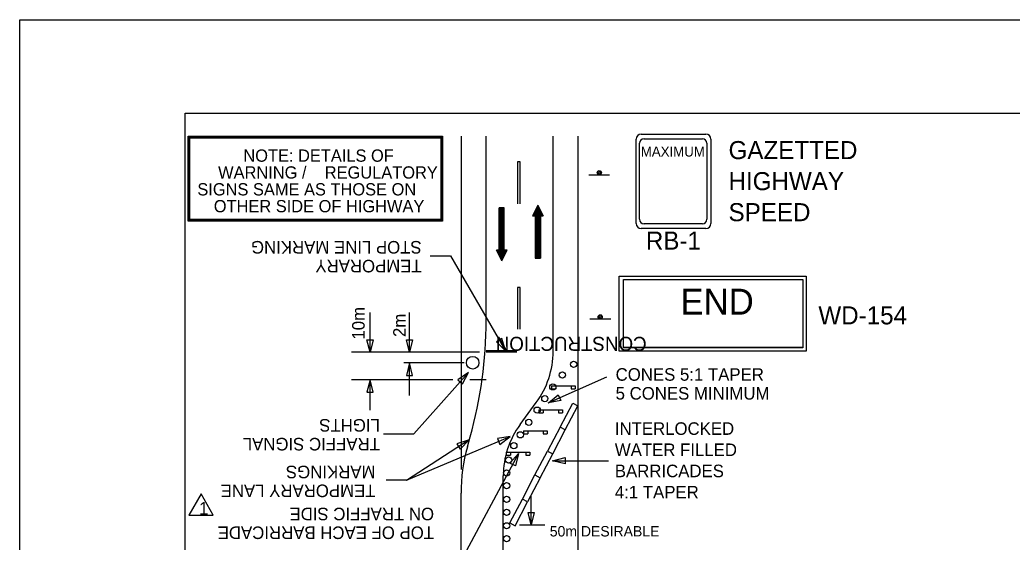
# Model space of a CAD drawing. Extents: x 2170 to 2386, y 134 to 413.
# Drawn here: x 2169.6 to 2284.4, y 352.3 to 412.8 of the extents above; entities that cross this region are included whole.
import ezdxf

# ---------------------------------------------------------------- set-up
doc = ezdxf.new("R2010")
doc.units = 0
for name, color, linetype in [('Level 1', 7, 'Continuous'), ('Level 10', 7, 'Continuous'), ('Level 2', 7, 'Continuous'), ('Level 44', 7, 'Continuous'), ('Level 5', 7, 'Continuous'), ('Level 60', 7, 'Continuous'), ('Level 7', 7, 'Continuous')]:
    doc.layers.add(name, color=color, linetype=linetype)

# ---------------------------------------------------------------- blocks, each defined once
blk = doc.blocks.new('END')
at = {"layer": 'Level 2'}
for points in [[(0, 8.676), (21.598, 8.676), (21.598, 0), (0, 0)], [(0.511, 8.287), (21.224, 8.287), (21.224, 0.397), (0.511, 0.397)]]:
    blk.add_lwpolyline(points, close=True, dxfattribs=at)
at = {"layer": 'Level 44'}
for s, height, rotation, p in [('END', 3, 359.99999, (7.085, 4.219)), ('CONSTRUCTION', 1.62, 179.99999, (3.164, 1.653))]:
    blk.add_text(s, height=height, rotation=rotation, dxfattribs=at).set_placement(p)
blk = doc.blocks.new('BARRIC')
at = {"layer": 'Level 2'}
for p, q in [((7.12, 10.29), (8.9, 12.87)), ((8.9, 12.87), (9.45, 12.48)), ((7.67, 9.91), (9.45, 12.48)), ((3.56, 5.15), (5.34, 7.72)), ((4.12, 4.76), (5.9, 7.33)), ((0, 0), (1.78, 2.57)), ((0.56, -0.39), (2.34, 2.19)), ((0, 0), (0.56, -0.39))]:
    blk.add_line(p, q, dxfattribs=at)
at = {"layer": 'Level 44'}
for p, q in [((7.12, 10.29), (5.34, 7.72)), ((5.9, 7.33), (7.67, 9.91)), ((7.67, 9.91), (7.12, 10.29)), ((5.34, 7.72), (5.9, 7.33)), ((1.78, 2.57), (3.56, 5.15)), ((4.12, 4.76), (2.34, 2.19)), ((3.56, 5.15), (4.12, 4.76)), ((2.34, 2.19), (1.78, 2.57))]:
    blk.add_line(p, q, dxfattribs=at)
blk = doc.blocks.new('REV1')
at = {"layer": 'Level 1'}
blk.add_lwpolyline([(0.114, 1.689), (-1.305, -0.781), (1.533, -0.781)], close=True, dxfattribs=at)
blk.add_text('1', height=1.448, rotation=360, dxfattribs=at).set_placement((-0.113, -0.724))

msp = doc.modelspace()

# ---------------------------------------------------------------- linework, layer by layer
at = {"layer": 'Level 10'}
for p, q in [((2220.64, 399.31), (2220.64, 360.72)), ((2223.55, 377.96), (2223.55, 399.31)), ((2231.29, 374.39), (2231.29, 399.28)), ((2234.19, 349.72), (2234.19, 399.31)), ((2225.04, 386.11), (2225.04, 391.01)), ((2225.65, 391.01), (2225.04, 391.01)), ((2225.04, 385.49), (2225.04, 391.01)), ((2225.12, 385.34), (2225.12, 391.01)), ((2225.19, 385.19), (2225.19, 391.01)), ((2225.27, 385.03), (2225.27, 391.01)), ((2225.35, 384.88), (2225.35, 391.01)), ((2225.42, 385.03), (2225.42, 391.01)), ((2225.5, 385.19), (2225.5, 391.01)), ((2225.58, 385.34), (2225.58, 391.01)), ((2225.65, 386.11), (2225.65, 391.01)), ((2225.65, 385.49), (2225.65, 391.01)), ((2229.54, 391.31), (2228.92, 390.08)), ((2229, 390.23), (2229, 390.08)), ((2229.08, 390.38), (2229.08, 390.08)), ((2229.15, 390.54), (2229.15, 390.08)), ((2229.23, 390.69), (2229.23, 385.17)), ((2229.31, 390.84), (2229.31, 385.17)), ((2229.38, 391), (2229.38, 385.17)), ((2229.46, 391.15), (2229.46, 385.17)), ((2229.54, 391.31), (2229.54, 385.17)), ((2229.54, 391.31), (2230.15, 390.08)), ((2229.61, 391.15), (2229.61, 385.17)), ((2229.69, 391), (2229.69, 385.17)), ((2229.77, 390.84), (2229.77, 385.17)), ((2229.84, 390.69), (2229.84, 385.17)), ((2229.92, 390.54), (2229.92, 390.08)), ((2230, 390.38), (2230, 390.08)), ((2230.07, 390.23), (2230.07, 390.08)), ((2228.92, 390.08), (2229.23, 390.08)), ((2229.23, 390.08), (2229.23, 385.17)), ((2229.84, 390.08), (2229.84, 385.17)), ((2229.84, 390.08), (2230.15, 390.08)), ((2225.35, 384.88), (2224.73, 386.11)), ((2225.04, 386.11), (2224.73, 386.11)), ((2224.81, 385.95), (2224.81, 386.11)), ((2224.89, 385.8), (2224.89, 386.11)), ((2224.96, 385.64), (2224.96, 386.11)), ((2225.35, 384.88), (2225.96, 386.11)), ((2225.96, 386.11), (2225.65, 386.11)), ((2225.73, 385.64), (2225.73, 386.11)), ((2225.81, 385.8), (2225.81, 386.11)), ((2225.88, 385.95), (2225.88, 386.11)), ((2217.08, 385.45), (2219.41, 385.45)), ((2219.41, 385.45), (2225.77, 374.45)), ((2229.23, 385.17), (2229.84, 385.17)), ((2210.12, 374.3), (2210.12, 378.89)), ((2214.68, 374.3), (2214.68, 378.89)), ((2222.79, 374.3), (2207.98, 374.3)), ((2227.09, 374.45), (2223.55, 374.45)), ((2227.09, 374.4), (2223.55, 374.4)), ((2227.09, 374.35), (2223.55, 374.35)), ((2227.09, 374.3), (2223.55, 374.3)), ((2221.02, 373.08), (2214.04, 373.08)), ((2214.68, 369.29), (2214.68, 373.08)), ((2215.2, 364.87), (2221.5, 371.95)), ((2219.69, 371.11), (2207.98, 371.11)), ((2210.12, 367.61), (2210.12, 371.11)), ((2223.55, 371.11), (2221.66, 371.11)), ((2231.11, 370.4), (2233.85, 370.4)), ((2231.11, 370.4), (2231.11, 370.06)), ((2231.11, 370.06), (2231.6, 370.06)), ((2231.6, 370.4), (2231.6, 370.06)), ((2233.37, 370.4), (2233.37, 370.06)), ((2233.37, 370.06), (2233.85, 370.06)), ((2233.85, 370.4), (2233.85, 370.06)), ((2227.48, 365.93), (2229.34, 368.47)), ((2229.64, 367.62), (2232.38, 367.62)), ((2229.64, 367.62), (2229.64, 367.28)), ((2229.64, 367.28), (2230.13, 367.28)), ((2230.13, 367.62), (2230.13, 367.28)), ((2231.9, 367.62), (2231.9, 367.28)), ((2231.9, 367.28), (2232.38, 367.28)), ((2232.38, 367.62), (2232.38, 367.28)), ((2227.88, 365.2), (2230.61, 365.2)), ((2227.88, 365.2), (2227.88, 364.86)), ((2228.36, 365.2), (2228.36, 364.86)), ((2230.13, 365.2), (2230.13, 364.86)), ((2230.61, 365.2), (2230.61, 364.86)), ((2211.67, 364.87), (2215.2, 364.87)), ((2221.58, 364.16), (2214.33, 359.46)), ((2214.35, 359.48), (2226.33, 364.54)), ((2221.38, 363.36), (2221.7, 364.51)), ((2227.88, 364.86), (2228.36, 364.86)), ((2230.13, 364.86), (2230.61, 364.86)), ((2225.87, 362.73), (2228.6, 362.73)), ((2225.87, 362.73), (2225.87, 362.39)), ((2226.35, 362.73), (2226.35, 362.39)), ((2228.12, 362.73), (2228.12, 362.39)), ((2228.6, 362.73), (2228.6, 362.39)), ((2227.3, 362.59), (2213.95, 337.69)), ((2225.87, 362.39), (2226.35, 362.39)), ((2228.12, 362.39), (2228.6, 362.39)), ((2231.22, 361.75), (2237.7, 361.75)), ((2214.33, 359.48), (2211.99, 359.48)), ((2220.64, 353.23), (2220.64, 357.98)), ((2228.76, 354.31), (2228.76, 357.65)), ((2227.42, 354.31), (2230.35, 354.31)), ((2220.64, 321.3), (2220.64, 353.23))]:
    msp.add_line(p, q, dxfattribs=at)
for points in [[(2210.49, 375.75), (2210.12, 374.3), (2209.76, 375.75)], [(2215.04, 375.75), (2214.68, 374.3), (2214.32, 375.75)], [(2224.73, 375.52), (2225.77, 374.45), (2225.36, 375.88)], [(2215.04, 371.62), (2214.68, 373.08), (2214.32, 371.62)], [(2220.81, 370.63), (2221.5, 371.95), (2220.27, 371.11)], [(2210.49, 369.66), (2210.12, 371.11), (2209.76, 369.66)], [(2220.54, 363.08), (2221.58, 364.16), (2220.15, 363.7)], [(2225.14, 363.64), (2226.33, 364.54), (2224.85, 364.31)], [(2226.3, 361.48), (2227.3, 362.59), (2226.94, 361.14)], [(2232.67, 361.38), (2231.22, 361.75), (2232.67, 362.11)], [(2229.12, 355.77), (2228.76, 354.31), (2228.39, 355.77)]]:
    msp.add_lwpolyline(points, close=True, dxfattribs=at)
for centre in [(2233.66, 372.9), (2232.37, 371.66), (2231.26, 370.29), (2230.33, 368.93), (2229.45, 367.6), (2228.48, 366.2), (2227.5, 364.74), (2226.75, 363.5), (2226.14, 361.84), (2225.92, 360.33), (2225.92, 358.85), (2225.92, 357.27), (2225.92, 355.78), (2225.92, 354.22), (2225.92, 352.73)]:
    msp.add_circle(centre, 0.359, dxfattribs=at)
at = {"layer": 'Level 2'}
for p, q in [((2227.18, 396.31), (2227.18, 391.47)), ((2227.47, 396.31), (2227.18, 396.31)), ((2227.47, 391.47), (2227.47, 396.31)), ((2227.18, 381.79), (2227.18, 376.95)), ((2227.47, 381.79), (2227.18, 381.79)), ((2227.47, 376.95), (2227.47, 381.79))]:
    msp.add_line(p, q, dxfattribs=at)
for points in [[(2238.94, 383.11), (2260.54, 383.11), (2260.54, 374.43), (2238.94, 374.43)], [(2239.45, 382.72), (2260.17, 382.72), (2260.17, 374.83), (2239.45, 374.83)]]:
    msp.add_lwpolyline(points, close=True, dxfattribs=at)
at = {"layer": 'Level 44'}
for p, q in [((2241.48, 399.53), (2248.97, 399.53)), ((2240.9, 389.19), (2240.9, 398.95)), ((2241.29, 389.68), (2241.29, 398.47)), ((2241.8, 398.99), (2248.55, 398.99)), ((2249.07, 398.47), (2249.07, 389.68)), ((2249.55, 398.95), (2249.55, 389.19)), ((2235.42, 394.81), (2237.82, 394.81)), ((2240.9, 389.18), (2240.9, 389.19)), ((2241.29, 389.68), (2241.29, 389.68)), ((2248.55, 389.16), (2241.8, 389.16)), ((2248.97, 388.6), (2241.48, 388.6)), ((2237.95, 378.12), (2235.55, 378.12))]:
    msp.add_line(p, q, dxfattribs=at)
for centre, radius in [((2236.63, 395.07), 0.24), ((2236.63, 395.07), 0.12), ((2236.74, 378.39), 0.24), ((2236.74, 378.39), 0.12), ((2221.99, 373.08), 0.726)]:
    msp.add_circle(centre, radius, dxfattribs=at)
for centre, radius, start, end in [((2241.48, 398.95), 0.578, 90, 180), ((2248.97, 398.95), 0.578, 360, 90), ((2241.81, 398.47), 0.52, 90, 180), ((2248.55, 398.47), 0.52, 360, 90), ((2241.48, 389.18), 0.578, 180, 270), ((2241.81, 389.68), 0.52, 180, 270), ((2248.55, 389.68), 0.52, 270, 360), ((2248.97, 389.18), 0.578, 270, 360)]:
    msp.add_arc(centre, radius, start, end, dxfattribs=at)
at = {"layer": 'Level 5'}
msp.add_line((2225.53, 313.63), (2225.53, 360), dxfattribs=at)
for centre, radius, start, end in [((2173.55, 377.96), 50, 344.3937, 0), ((2221.29, 374.39), 10, 323.6679, 0), ((2235.53, 360), 10, 143.6679, 180), ((2240.64, 357.98), 20, 164.3937, 180)]:
    msp.add_arc(centre, radius, start, end, dxfattribs=at)
at = {"layer": 'Level 60'}
msp.add_line((2169.62, 412.76), (2169.62, 412.76), dxfattribs=at)
for points in [[(2169.62, 412.76), (2385.62, 412.76), (2385.62, 133.76), (2169.62, 133.76)], [(2188.75, 401.95), (2375.62, 401.95), (2375.62, 144.57), (2188.75, 144.57)]]:
    msp.add_lwpolyline(points, close=True, dxfattribs=at)
at = {"layer": 'Level 7'}
msp.add_line((2230.73, 368.45), (2237.49, 371.46), dxfattribs=at)
for points in [[(2189.09, 399.29), (2218.5, 399.29), (2218.5, 389.46), (2189.09, 389.46)], [(2189.19, 399.19), (2218.4, 399.19), (2218.4, 389.56), (2189.19, 389.56)], [(2189.29, 399.09), (2218.3, 399.09), (2218.3, 389.66), (2189.29, 389.66)], [(2232.18, 368.71), (2230.74, 368.45), (2231.89, 369.36)]]:
    msp.add_lwpolyline(points, close=True, dxfattribs=at)

# ---------------------------------------------------------------- block references
at = {"layer": 'Level 1'}
msp.add_blockref('REV1', (2190.46, 356.24), dxfattribs=at)
at = {"layer": 'Level 2'}
msp.add_blockref('END', (2238.94, 374.43), dxfattribs=at)
at = {"layer": 'Level 2', "rotation": 6.999999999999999}
msp.add_blockref('BARRIC', (2226.29, 354.55), dxfattribs=at)

# ---------------------------------------------------------------- texts
at = {"layer": 'Level 10'}
for s, height, p in [('GAZETTED ', 2.09, (2251.58, 396.64)), ('HIGHWAY', 2.09, (2251.58, 393.05)), ('SPEED', 2.09, (2251.58, 389.46)), ('RB-1', 2.09, (2242.02, 386.17)), ('WD-154', 2.09, (2261.97, 377.52)), ('CONES 5:1 TAPER', 1.4514, (2238.52, 371)), ('5 CONES MINIMUM', 1.4514, (2238.52, 368.82)), ('INTERLOCKED', 1.451, (2238.43, 364.74)), ('WATER FILLED', 1.451, (2238.43, 362.29)), ('BARRICADES', 1.451, (2238.43, 359.84)), ('4:1 TAPER', 1.451, (2238.43, 357.39))]:
    msp.add_text(s, height=height, dxfattribs=at).set_placement(p)
for s, height, rotation, p in [('STOP LINE MARKING', 1.4514, 180, (2216.09, 387.17)), ('TEMPORARY', 1.451, 180, (2216.09, 384.99)), ('10m', 1.451, 90, (2209.5, 375.76)), ('2m', 1.451, 90, (2214.25, 376.06)), ('LIGHTS', 1.451, 180, (2211.26, 366.57)), ('TRAFFIC SIGNAL ', 1.4514, 180, (2211.26, 364.39)), ('MARKINGS', 1.451, 180, (2210.75, 361.17)), ('TEMPORARY LANE', 1.4514, 180, (2210.75, 358.99)), ('ON TRAFFIC SIDE', 1.4514, 180, (2217.52, 356.31)), ('TOP OF EACH BARRICADE', 1.4514, 180, (2217.52, 354.14))]:
    msp.add_text(s, height=height, rotation=rotation, dxfattribs=at).set_placement(p)
at = {"layer": 'Level 44'}
for s, height, rotation, p in [('MAXIMUM', 1.147, 360, (2241.43, 396.94)), ('CONSTRUCTION', 1.6202, 180, (2242.11, 376.08))]:
    msp.add_text(s, height=height, rotation=rotation, dxfattribs=at).set_placement(p)
msp.add_text('50m DESIRABLE', height=1.2095, dxfattribs=at).set_placement((2230.91, 352.98))
at = {"layer": 'Level 7'}
for s, p in [('NOTE: DETAILS OF ', (2195.47, 396.34)), ('WARNING /    REGULATORY', (2192.55, 394.39)), ('SIGNS SAME AS THOSE ON  ', (2190.15, 392.44)), ('OTHER SIDE OF HIGHWAY', (2192.05, 390.49))]:
    msp.add_text(s, height=1.419, dxfattribs=at).set_placement(p)

doc.saveas('drawing.dxf')
